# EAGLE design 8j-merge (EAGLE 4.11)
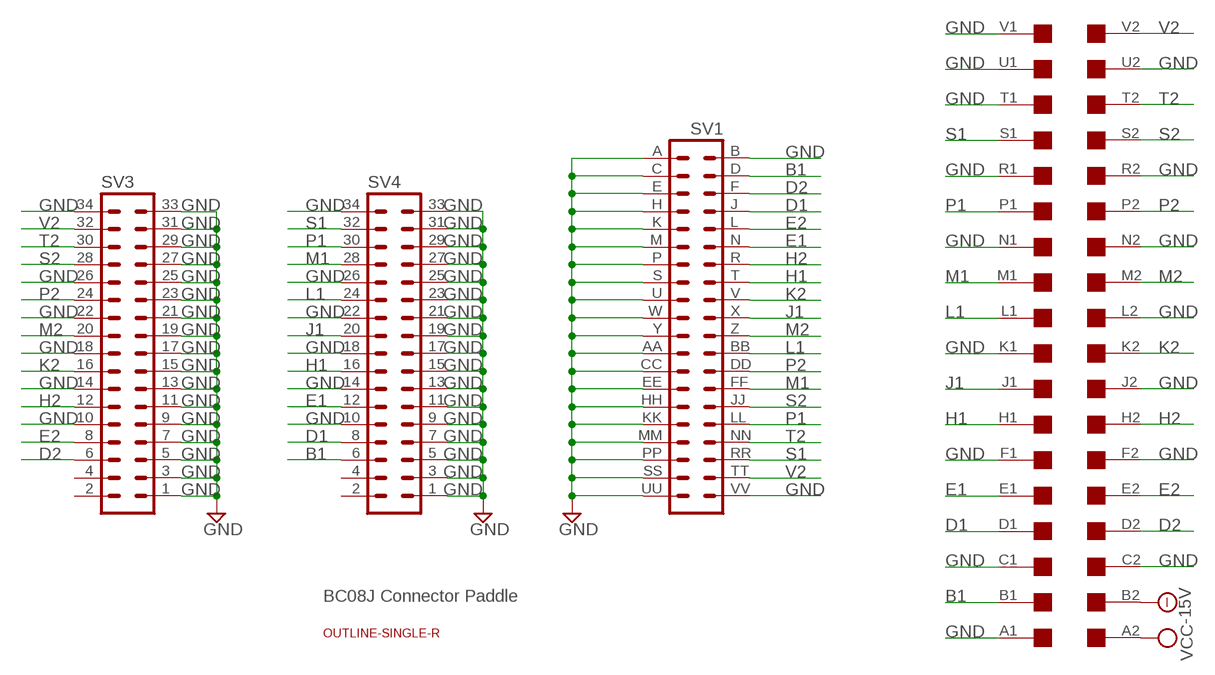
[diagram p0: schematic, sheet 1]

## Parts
SV1  DEC40PIN  [DEC40PIN]
SV3  MA17-2  [MA17-2]
SV4  MA17-2  [MA17-2]
U$1  OUTLINE-SINGLE-R  [SINGLE-R]
U$2  SINGLE  [EDGE-CON2]

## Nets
-15V: U$2.B2
B1: SV1.D SV4.6 U$2.B1
D1: SV1.J SV4.8 U$2.D1
D2: SV1.F SV3.6 U$2.D2
E1: SV1.N SV4.12 U$2.E1
E2: SV1.L SV3.8 U$2.E2
GND: SV1.A SV1.AA SV1.B SV1.C SV1.CC SV1.E SV1.EE SV1.H SV1.HH SV1.K SV1.KK SV1.M SV1.MM SV1.P SV1.PP SV1.S SV1.SS SV1.U SV1.UU SV1.VV SV1.W SV1.Y SV3.1 SV3.3 SV3.5 SV3.7 SV3.9 SV3.10 SV3.11 SV3.13 SV3.14 SV3.15 SV3.17 SV3.18 SV3.19 SV3.21 SV3.22 SV3.23 SV3.25 SV3.26 SV3.27 SV3.29 SV3.31 SV3.33 SV3.34 SV4.1 SV4.3 SV4.5 SV4.7 SV4.9 SV4.10 SV4.11 SV4.13 SV4.14 SV4.15 SV4.17 SV4.18 SV4.19 SV4.21 SV4.22 SV4.23 SV4.25 SV4.26 SV4.27 SV4.29 SV4.31 SV4.33 SV4.34 U$2.A1 U$2.C1 U$2.C2 U$2.F1 U$2.F2 U$2.J2 U$2.K1 U$2.L2 U$2.N1 U$2.N2 U$2.R1 U$2.R2 U$2.T1 U$2.U1 U$2.U2 U$2.V1
H1: SV1.T SV4.16 U$2.H1
H2: SV1.R SV3.12 U$2.H2
J1: SV1.X SV4.20 U$2.J1
K2: SV1.V SV3.16 U$2.K2
L1: SV1.BB SV4.24 U$2.L1
M1: SV1.FF SV4.28 U$2.M1
M2: SV1.Z SV3.20 U$2.M2
P1: SV1.LL SV4.30 U$2.P1
P2: SV1.DD SV3.24 U$2.P2
S1: SV1.RR SV4.32 U$2.S1
S2: SV1.JJ SV3.28 U$2.S2
T2: SV1.NN SV3.30 U$2.T2
V2: SV1.TT SV3.32 U$2.V2
VCC: U$2.A2
Unconnected: SV3.2 SV3.4 SV4.2 SV4.4

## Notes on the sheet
- BC08J Connector Paddle

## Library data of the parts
SV1 = dec-con:DEC40PIN: PIN HEADER
SV3 SV4 = con-lstb:MA17-2: PIN HEADER
U$1 = dec-con:OUTLINE-*: Board outlines for DEC boards.
U$2 = dec-con:SINGLE: Double-Height DEC board

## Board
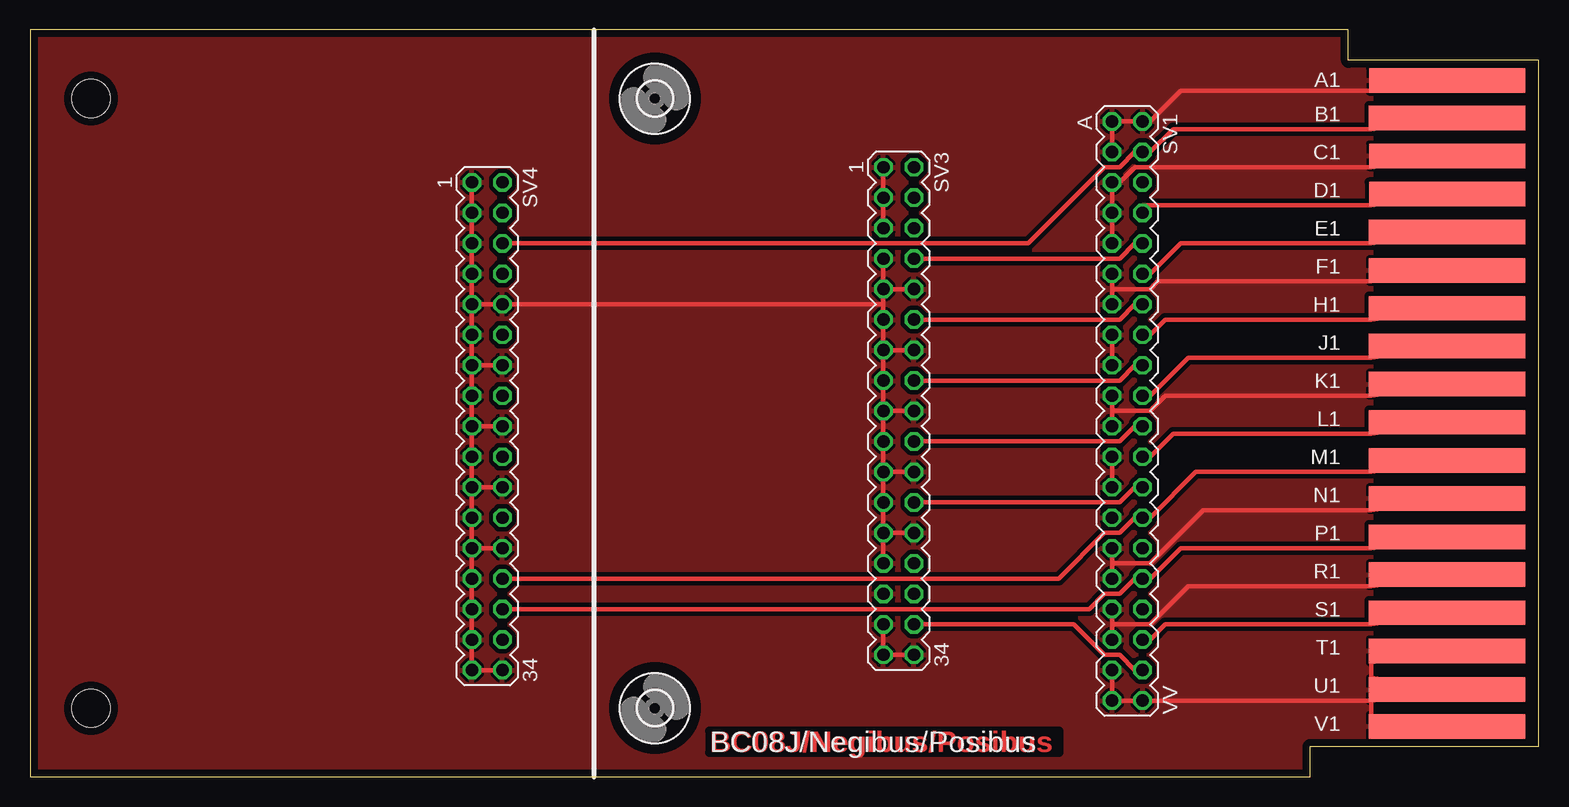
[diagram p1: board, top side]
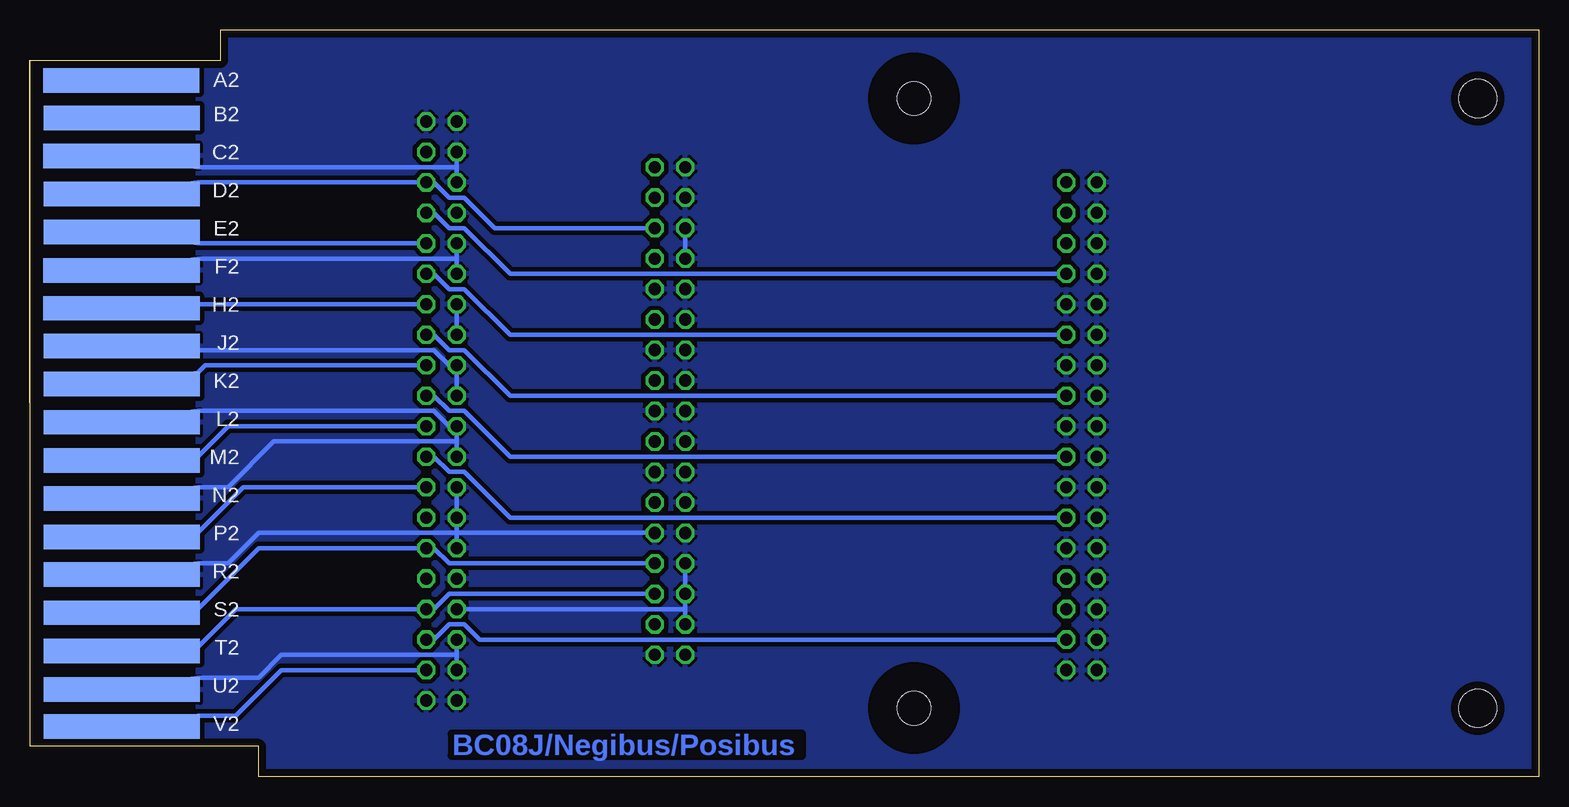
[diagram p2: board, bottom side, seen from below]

Size 125.73 x 62.23 mm. Coordinates in mm from the lower left corner, seen from the top.
Copper layers (1*16): Top 0.035mm / dielectric 1.5mm / Bottom 0.035mm
Design rules "olimex10mil": minimum track width 15mil, minimum drill 24mil, track to track 15mil, track to pad 10mil, pad to pad 10mil, via to via 10mil, smd to smd 10mil, copper to edge 25mil, drill to drill 10mil, minimum pad ring 10mil, minimum via ring 8mil, stop-mask expansion 0mil, vias tented up to drill 0mil, thermal gap 10mil

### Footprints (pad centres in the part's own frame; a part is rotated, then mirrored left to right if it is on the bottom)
DEC40PIN = drill 1.016 octagon: A -24.13,-1.27; AA 3.81,-1.27; B -24.13,1.27; BB 3.81,1.27; C -21.59,-1.27; CC 6.35,-1.27; D -21.59,1.27; DD 6.35,1.27; E -19.05,-1.27; EE 8.89,-1.27; F -19.05,1.27; FF 8.89,1.27; H -16.51,-1.27; HH 11.43,-1.27; J -16.51,1.27; JJ 11.43,1.27; K -13.97,-1.27; KK 13.97,-1.27; L -13.97,1.27; LL 13.97,1.27; M -11.43,-1.27; MM 16.51,-1.27; N -11.43,1.27; NN 16.51,1.27; P -8.89,-1.27; PP 19.05,-1.27; R -8.89,1.27; RR 19.05,1.27; S -6.35,-1.27; SS 21.59,-1.27; T -6.35,1.27; TT 21.59,1.27; U -3.81,-1.27; UU 24.13,-1.27; V -3.81,1.27; VV 24.13,1.27; W -1.27,-1.27; X -1.27,1.27; Y 1.27,-1.27; Z 1.27,1.27
MA17-2 = drill 1.016 octagon: 1 -20.32,-1.27; 2 -20.32,1.27; 3 -17.78,-1.27; 4 -17.78,1.27; 5 -15.24,-1.27; 6 -15.24,1.27; 7 -12.7,-1.27; 8 -12.7,1.27; 9 -10.16,-1.27; 10 -10.16,1.27; 11 -7.62,-1.27; 12 -7.62,1.27; 13 -5.08,-1.27; 14 -5.08,1.27; 15 -2.54,-1.27; 16 -2.54,1.27; 17 0,-1.27; 18 0,1.27; 19 2.54,-1.27; 20 2.54,1.27; 21 5.08,-1.27; 22 5.08,1.27; 23 7.62,-1.27; 24 7.62,1.27; 25 10.16,-1.27; 26 10.16,1.27; 27 12.7,-1.27; 28 12.7,1.27; 29 15.24,-1.27; 30 15.24,1.27; 31 17.78,-1.27; 32 17.78,1.27; 33 20.32,-1.27; 34 20.32,1.27
SINGLE-R = hole 3.175: 5.08,5.715; 5.08,56.515
EDGE-CON2 = smd 13.017 x 2.032: A1 7.633,4.207; B1 7.639,7.327; C1 7.636,10.489; D1 7.633,13.665; E1 7.642,16.84; F1 7.642,20.041; H1 7.642,23.19; J1 7.642,26.34; K1 7.642,29.515; L1 7.642,32.69; M1 7.642,35.89; N1 7.642,39.04; P1 7.642,42.24; R1 7.642,45.39; S1 7.642,48.565; T1 7.642,51.74; U1 7.642,54.966; V1 7.642,58.026 | smd 13.017 x 2.032 bottom: A2 7.614,4.207; B2 7.642,7.328; C2 7.617,10.49; D2 7.642,13.665; E2 7.642,16.84; F2 7.617,20.041; H2 7.617,23.19; J2 7.642,26.34; K2 7.642,29.515; L2 7.642,32.69; M2 7.642,35.89; N2 7.642,39.04; P2 7.642,42.24; R2 7.642,45.39; S2 7.642,48.565; T2 7.642,51.74; U2 7.642,54.966; V2 7.642,58.026
2,8 = hole 2.8: 0,0

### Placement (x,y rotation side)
SV1  91.44,30.48 270 top
SV3  72.39,30.48 270 top
SV4  38.1,29.21 270 top
U$1  0,0 0 top
U$2  125.73,62.23 180 top
U$3  [2,8]  52.07,56.52 0 top
U$4  [2,8]  52.07,5.71 0 top

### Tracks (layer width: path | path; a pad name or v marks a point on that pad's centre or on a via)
B1
  Top 0.381: SV4.6 40.01,44.45 83.19,44.45 89.53,50.8 90.81,50.8 92.08,52.07 SV1.D 93.34,52.07 95.25,53.98 111.76,53.98 U$2.B1
D1
  Top 0.381: U$2.D1 111.76,47.62 92.71,47.62 SV1.J
  Bottom 0.381: SV4.8 40.01,41.91 85.72,41.91 89.53,45.72 90.81,45.72 92.08,46.99 SV1.J
D2
  Bottom 0.381: SV3.6 74.3,45.72 87,45.72 89.53,48.26 90.81,48.26 92.08,49.53 SV1.F 93.34,49.53 111.76,49.53 U$2.D2
E1
  Top 0.381: U$2.E1 111.76,44.45 95.89,44.45 93.34,41.91 SV1.N
  Bottom 0.381: SV4.12 40.01,36.83 85.72,36.83 89.53,40.64 90.81,40.64 92.08,41.91 SV1.N
E2
  Top 0.381: SV3.8 74.3,43.18 90.81,43.18 92.08,44.45 SV1.L
  Bottom 0.381: SV1.L 93.34,44.45 111.76,44.45 U$2.E2
GND
  Top 0.381: 90.17,17.78 90.17,18.41 SV1.HH | 90.17,17.78 90.17,17.14 SV1.KK | SV1.AA 90.17,26.04 90.17,24.77 SV1.CC | 90.17,30.48 90.17,29.84 SV1.Y | 90.17,30.48 90.17,31.11 SV1.W | SV1.S 90.17,36.2 90.17,34.92 SV1.U | 90.17,40.64 90.17,40.01 SV1.P | 90.17,40.64 90.17,41.27 SV1.M | SV1.K 90.17,45.09 90.17,46.35 SV1.H 90.17,47.62 90.17,48.9 SV1.E 90.81,49.53 92.08,50.8 111.76,50.8 U$2.C1 | SV1.C 90.17,52.7 90.17,53.98 SV1.A 90.81,54.61 92.08,54.61 SV1.B 93.34,54.61 95.89,57.15 111.76,57.15 U$2.A1 | 90.17,17.78 93.34,17.78 97.79,22.23 111.76,22.23 U$2.N1 | 90.17,30.48 93.34,30.48 94.61,31.75 111.76,31.75 U$2.K1 | 90.17,40.64 93.34,40.64 93.98,41.27 111.76,41.27 U$2.F1 | SV4.34 38.73,8.89 37.47,8.89 SV4.33 36.83,9.53 36.83,10.79 SV4.31 36.83,12.06 36.83,13.34 SV4.29 36.83,14.61 36.83,15.88 SV4.27 36.83,17.14 36.83,18.41 SV4.25 | SV4.26 38.73,19.05 37.47,19.05 SV4.25 | SV4.25 36.83,19.68 36.83,20.95 SV4.23 36.83,22.23 36.83,23.5 SV4.21 | SV4.22 38.73,24.13 37.47,24.13 SV4.21 | SV4.21 36.83,24.77 36.83,26.04 SV4.19 36.83,27.3 36.83,28.57 SV4.17 | SV4.18 38.73,29.21 37.47,29.21 SV4.17 | SV4.17 36.83,29.84 36.83,31.11 SV4.15 36.83,32.38 36.83,33.66 SV4.13 | SV4.14 38.73,34.29 37.47,34.29 SV4.13 | SV4.13 36.83,34.92 36.83,36.2 SV4.11 36.83,37.47 36.83,38.73 SV4.9 | SV4.9 37.47,39.37 38.73,39.37 SV4.10 40.01,39.37 71.12,39.37 | SV4.9 36.83,40.01 36.83,41.27 SV4.7 36.83,42.55 36.83,43.81 SV4.5 36.83,45.09 36.83,46.35 SV4.3 36.83,47.62 36.83,48.9 SV4.1 | 111.76,6.35 111.76,5.08 U$2.V1 | 111.76,6.35 U$2.U1 | U$2.T1 111.76,9.53 111.76,8.26 U$2.U1 | SV1.SS 90.17,8.26 90.17,6.99 SV1.UU 90.81,6.35 92.08,6.35 SV1.VV 93.34,6.35 111.76,6.35
  Top 0.381: 90.17,12.7 90.17,12.06 SV1.PP | 90.17,12.7 90.17,13.34 SV1.MM | SV3.34 73.03,10.16 71.75,10.16 SV3.33 71.12,10.79 71.12,12.06 SV3.31 | SV3.25 71.12,19.68 71.12,18.41 SV3.27 | SV3.25 71.12,20.95 71.12,22.23 SV3.23 71.12,23.5 71.12,24.77 SV3.21 | SV3.26 73.03,20.32 71.75,20.32 SV3.25 | SV3.22 73.03,25.4 71.75,25.4 SV3.21 | SV3.21 71.12,26.04 71.12,27.3 SV3.19 71.12,28.57 71.12,29.84 SV3.17 | SV3.17 71.12,31.11 71.12,32.38 SV3.15 71.12,33.66 71.12,34.92 SV3.13 | SV3.18 73.03,30.48 71.75,30.48 SV3.17 | SV3.14 73.03,35.56 71.75,35.56 SV3.13 | SV3.13 71.12,36.2 71.12,37.47 SV3.11 71.12,38.73 71.12,39.37 | 71.12,39.37 71.12,40.01 SV3.9 | SV3.10 73.03,40.64 71.75,40.64 SV3.9 | SV3.7 71.12,42.55 71.12,41.27 SV3.9 | SV3.5 71.12,46.35 71.12,47.62 SV3.3 71.12,48.9 71.12,50.16 SV3.1 | 90.17,12.7 93.34,12.7 96.52,15.88 111.76,15.88 U$2.R1 | 111.76,6.35 U$2.U1
  Bottom 0.381: 90.17,20.32 90.17,19.68 SV1.HH | 90.17,20.32 90.17,20.95 SV1.EE 90.17,22.23 90.17,23.5 SV1.CC | 90.17,27.94 90.17,27.3 SV1.AA | 90.17,27.94 90.17,28.57 SV1.Y 90.81,29.21 92.08,30.48 111.76,30.48 U$2.L2 | SV1.W 90.17,32.38 90.17,33.66 SV1.U 90.81,34.29 92.08,35.56 111.76,35.56 U$2.J2 | SV1.P 90.17,38.73 90.17,37.47 SV1.S | 90.17,43.18 90.17,42.55 SV1.M | 90.17,43.18 90.17,43.81 SV1.K | 90.17,50.8 90.17,50.16 SV1.E | 90.17,50.8 90.17,51.44 SV1.C | 90.17,20.32 106.68,20.32 109.22,17.78 111.76,17.78 U$2.R1 | 90.17,27.94 105.41,27.94 109.22,24.13 111.76,24.13 U$2.N1 | 90.17,43.18 111.76,43.18 U$2.F2 | 90.17,50.8 111.76,50.8 U$2.C2 | 90.17,10.16 90.17,10.79 SV1.PP | 90.17,10.16 90.17,9.53 SV1.SS | 71.12,13.97 71.12,13.34 SV3.31 | 71.12,13.97 71.12,14.61 SV3.29 71.12,15.88 71.12,17.14 SV3.27 | SV3.5 71.12,45.09 71.12,43.81 SV3.7 | 71.12,13.97 89.53,13.97 SV1.MM | 90.17,20.32 74.3,20.32 SV3.26 | 90.17,10.16 104.78,10.16 106.68,8.26 111.76,8.26 U$2.U1
  pour Bottom (isolate 0.254): 0,62.23 111.76,62.23 111.76,0 0,0
  pour Top (isolate 0.254): 111.76,62.23 0,62.23 0,0 111.76,0
H1
  Top 0.381: U$2.H1 111.76,38.1 94.61,38.1 93.34,36.83 SV1.T
  Bottom 0.381: SV4.16 40.01,31.75 85.72,31.75 89.53,35.56 90.81,35.56 92.08,36.83 SV1.T
H2
  Top 0.381: SV3.12 74.3,38.1 90.81,38.1 92.08,39.37 SV1.R
  Bottom 0.381: SV1.R 93.34,39.37 111.76,39.37 U$2.H2
J1
  Top 0.381: U$2.J1 111.76,34.92 96.52,34.92 93.34,31.75 SV1.X
  Bottom 0.381: SV4.20 40.01,26.67 85.72,26.67 89.53,30.48 90.81,30.48 92.08,31.75 SV1.X
K2
  Top 0.381: SV3.16 74.3,33.02 90.81,33.02 92.08,34.29 SV1.V
  Bottom 0.381: SV1.V 93.34,34.29 111.12,34.29 111.76,33.66 U$2.K2
L1
  Top 0.381: U$2.L1 111.76,28.57 95.25,28.57 93.34,26.67 SV1.BB
  Bottom 0.381: SV4.24 40.01,21.59 85.72,21.59 89.53,25.4 90.81,25.4 92.08,26.67 SV1.BB
M1
  Top 0.381: SV4.28 40.01,16.51 85.72,16.51 89.53,20.32 90.81,20.32 92.08,21.59 SV1.FF 93.34,21.59 97.16,25.4 111.76,25.4 U$2.M1
M2
  Top 0.381: SV3.20 74.3,27.94 90.81,27.94 92.08,29.21 SV1.Z
  Bottom 0.381: SV1.Z 93.34,29.21 109.22,29.21 111.76,26.67 U$2.M2
P1
  Top 0.381: SV4.30 40.01,13.97 88.27,13.97 89.53,15.24 90.81,15.24 92.08,16.51 SV1.LL 93.34,16.51 95.89,19.05 111.76,19.05 U$2.P1
P2
  Top 0.381: SV3.24 74.3,22.86 90.81,22.86 92.08,24.13 SV1.DD
  Bottom 0.381: SV1.DD 93.34,24.13 107.95,24.13 111.76,20.32 U$2.P2
S1
  Top 0.381: U$2.S1 111.76,12.7 94.61,12.7 93.34,11.43 SV1.RR
  Bottom 0.381: SV4.32 40.01,11.43 88.27,11.43 89.53,12.7 90.81,12.7 92.08,11.43 SV1.RR
S2
  Bottom 0.381: SV3.28 74.3,17.78 90.81,17.78 92.08,19.05 SV1.JJ 93.34,19.05 106.68,19.05 111.76,13.97 U$2.S2
T2
  Bottom 0.381: SV3.30 74.3,15.24 90.81,15.24 92.08,13.97 SV1.NN 93.34,13.97 108.58,13.97 111.76,10.79 U$2.T2
V2
  Top 0.381: SV3.32 74.3,12.7 87,12.7 89.53,10.16 90.81,10.16 92.08,8.89 SV1.TT
  Bottom 0.381: SV1.TT 93.34,8.89 104.78,8.89 108.58,5.08 111.76,5.08 U$2.V2

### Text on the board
Top: BC08J/Negibus/Posibus
Bottom: BC08J/Negibus/Posibus
tPlace: BC08J/Negibus/Posibus
tValues: * | * | * | * | * | * | * | * | * | * | * | * | Side 1 | Side 2 | * | * | * | * | * | * | * | BC08J | * | * | * | * | * | * | * | * | * | * | * | * | * | * | * | * | *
